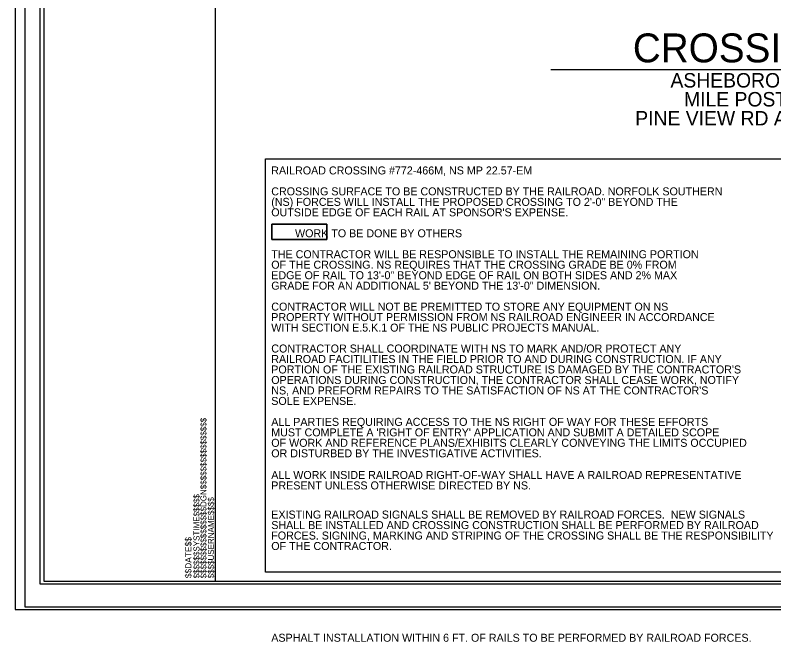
# Model space of a CAD drawing. Extents: x 1756964 to 1757438, y 736785 to 737067.
# Drawn here: x 1756963.6 to 1757129.6, y 736784.9 to 736922.2 of the extents above; entities that cross this region are included whole.
import ezdxf

# ---------------------------------------------------------------- set-up
doc = ezdxf.new("R2010")
doc.units = 0
for name, color, linetype in [('Old_Level_41', 7, 'Continuous'), ('Old_Level_62', 7, 'Continuous'), ('Old_Level_63', 7, 'Continuous'), ('Old_Level_7', 7, 'Continuous'), ('Prop DSN Text', 7, 'Continuous'), ('Prop DSN White Annotation Label', 7, 'Continuous'), ('Prop Shade Light', 7, 'Continuous'), ('Sheet Plan CELL', 7, 'Continuous'), ('Sheet Plot Border Inside CELL', 7, 'Continuous'), ('Sheet Plot Border Outside CELL', 7, 'Continuous')]:
    doc.layers.add(name, color=color, linetype=linetype)

msp = doc.modelspace()

# ---------------------------------------------------------------- linework, layer by layer
at = {"layer": 'Old_Level_62'}
msp.add_lwpolyline([(1756969.89, 736798.25), (1757382.39, 736798.25), (1757382.39, 737060.75), (1756969.89, 737060.75)], close=True, dxfattribs=at)
at = {"layer": 'Old_Level_63'}
msp.add_lwpolyline([(1757388.64, 737067), (1756963.64, 737067), (1756963.64, 736792), (1757388.64, 736792)], close=True, dxfattribs=at)
at = {"layer": 'Old_Level_7'}
msp.add_lwpolyline([(1757019.79, 736873.02), (1757031.84, 736873.02), (1757031.84, 736876.41), (1757019.79, 736876.41), (1757019.79, 736873.02)], dxfattribs=at)
at = {"layer": 'Prop DSN Text'}
msp.add_line((1757080.82, 736910.24), (1757195.1, 736910.24), dxfattribs=at)
at = {"layer": 'Prop DSN White Annotation Label'}
msp.add_lwpolyline([(1757018.39, 736890.67), (1757131.72, 736890.67), (1757131.72, 736800.23), (1757018.39, 736800.23)], close=True, dxfattribs=at)
at = {"layer": 'Prop Shade Light'}
msp.add_lwpolyline([(1757019.79, 736876.41), (1757031.84, 736876.41), (1757031.84, 736873.02), (1757019.79, 736873.02)], close=True, dxfattribs=at)
at = {"layer": 'Sheet Plan CELL'}
msp.add_line((1757007.39, 736798.25), (1757007.39, 736798.25), dxfattribs=at)
msp.add_lwpolyline([(1757382.4, 737060.75), (1757007.39, 737060.75), (1757007.39, 736798.25), (1757382.39, 736798.25)], close=True, dxfattribs=at)
at = {"layer": 'Sheet Plot Border Inside CELL'}
msp.add_lwpolyline([(1756969.02, 736797.62), (1757385.52, 736797.62), (1757385.52, 737061.37), (1756969.02, 737061.37)], close=True, dxfattribs=at)
at = {"layer": 'Sheet Plot Border Outside CELL'}
msp.add_lwpolyline([(1756965.77, 736792.62), (1757386.64, 736792.62), (1757386.64, 737066.37), (1756965.77, 737066.37)], close=True, dxfattribs=at)

# ---------------------------------------------------------------- texts
at = {"layer": 'Old_Level_41'}
msp.add_text('$$DATE$$', height=1.378, rotation=90, dxfattribs=at).set_placement((1757002.21, 736798.87))
at = {"layer": 'Prop DSN Text'}
for s, height, p in [('CROSSING DETAIL', 6.3281, (1757098.75, 736911.82)), ('ASHEBORO, NC - #772-466M', 3.1641, (1757106.98, 736906.31)), ('MILE POST NS M-22.57-EM', 3.1641, (1757109.94, 736902.16)), ('PINE VIEW RD AT-GRADE CROSSING', 3.1641, (1757099.27, 736898.01))]:
    msp.add_text(s, height=height, rotation=360, dxfattribs=at).set_placement(p)
at = {"layer": 'Prop DSN White Annotation Label'}
for s, p in [('RAILROAD CROSSING #772-466M, NS MP 22.57-EM', (1757019.66, 736887.28)), ('CROSSING SURFACE TO BE CONSTRUCTED BY THE RAILROAD. NORFOLK SOUTHERN ', (1757019.66, 736882.7)), ('(NS) FORCES WILL INSTALL THE PROPOSED CROSSING TO 2\'-0" BEYOND THE ', (1757019.66, 736880.4)), ("OUTSIDE EDGE OF EACH RAIL AT SPONSOR'S EXPENSE.", (1757019.66, 736878.11)), ('        WORK TO BE DONE BY OTHERS', (1757019.66, 736873.52)), ('THE CONTRACTOR WILL BE RESPONSIBLE TO INSTALL THE REMAINING PORTION ', (1757019.66, 736868.93)), ('OF THE CROSSING. NS REQUIRES THAT THE CROSSING GRADE BE 0% FROM ', (1757019.66, 736866.64)), ('EDGE OF RAIL TO 13\'-0" BEYOND EDGE OF RAIL ON BOTH SIDES AND 2% MAX', (1757019.66, 736864.34)), ('GRADE FOR AN ADDITIONAL 5\' BEYOND THE 13\'-0" DIMENSION.', (1757019.66, 736862.05)), ('CONTRACTOR WILL NOT BE PREMITTED TO STORE ANY EQUIPMENT ON NS ', (1757019.66, 736857.46)), ('PROPERTY WITHOUT PERMISSION FROM NS RAILROAD ENGINEER IN ACCORDANCE ', (1757019.66, 736855.17)), ('WITH SECTION E.5.K.1 OF THE NS PUBLIC PROJECTS MANUAL.', (1757019.66, 736852.87)), ('CONTRACTOR SHALL COORDINATE WITH NS TO MARK AND/OR PROTECT ANY', (1757019.66, 736848.29)), ('RAILROAD FACITILITIES IN THE FIELD PRIOR TO AND DURING CONSTRUCTION. IF ANY', (1757019.66, 736845.99)), ("PORTION OF THE EXISTING RAILROAD STRUCTURE IS DAMAGED BY THE CONTRACTOR'S ", (1757019.66, 736843.7)), ('OPERATIONS DURING CONSTRUCTION, THE CONTRACTOR SHALL CEASE WORK, NOTIFY ', (1757019.66, 736841.4)), ("NS, AND PREFORM REPAIRS TO THE SATISFACTION OF NS AT THE CONTRACTOR'S ", (1757019.66, 736839.11)), ('SOLE EXPENSE.', (1757019.66, 736836.81)), ('ALL PARTIES REQUIRING ACCESS TO THE NS RIGHT OF WAY FOR THESE EFFORTS ', (1757019.66, 736832.23)), ("MUST COMPLETE A 'RIGHT OF ENTRY' APPLICATION AND SUBMIT A DETAILED SCOPE ", (1757019.66, 736829.93)), ('OF WORK AND REFERENCE PLANS/EXHIBITS CLEARLY CONVEYING THE LIMITS OCCUPIED ', (1757019.66, 736827.64)), ('OR DISTURBED BY THE INVESTIGATIVE ACTIVITIES.', (1757019.66, 736825.34)), ('ALL WORK INSIDE RAILROAD RIGHT-OF-WAY SHALL HAVE A RAILROAD REPRESENTATIVE ', (1757019.66, 736820.6)), ('PRESENT UNLESS OTHERWISE DIRECTED BY NS.', (1757019.66, 736818.31)), ('EXISTING RAILROAD SIGNALS SHALL BE REMOVED BY RAILROAD FORCES.  NEW SIGNALS ', (1757019.66, 736811.93)), ('SHALL BE INSTALLED AND CROSSING CONSTRUCTION SHALL BE PERFORMED BY RAILROAD ', (1757019.66, 736809.63)), ('FORCES. SIGNING, MARKING AND STRIPING OF THE CROSSING SHALL BE THE RESPONSIBILITY ', (1757019.66, 736807.34)), ('OF THE CONTRACTOR.', (1757019.66, 736805.05)), ('ASPHALT INSTALLATION WITHIN 6 FT. OF RAILS TO BE PERFORMED BY RAILROAD FORCES.', (1757019.66, 736784.96))]:
    msp.add_text(s, height=1.75, rotation=360, dxfattribs=at).set_placement(p)
at = {"layer": 'Sheet Plan CELL'}
for s, p in [('$$$$$$$$$$$$$$$$DGN$$$$$$$$$$$$$$$$', (1757005.48, 736798.84)), ('$$$$$$SYSTIME$$$$$', (1757003.96, 736798.83)), ('$$$$USERNAME$$$$', (1757007.12, 736798.84))]:
    msp.add_text(s, height=1.3125, rotation=90, dxfattribs=at).set_placement(p)

doc.saveas('drawing.dxf')
